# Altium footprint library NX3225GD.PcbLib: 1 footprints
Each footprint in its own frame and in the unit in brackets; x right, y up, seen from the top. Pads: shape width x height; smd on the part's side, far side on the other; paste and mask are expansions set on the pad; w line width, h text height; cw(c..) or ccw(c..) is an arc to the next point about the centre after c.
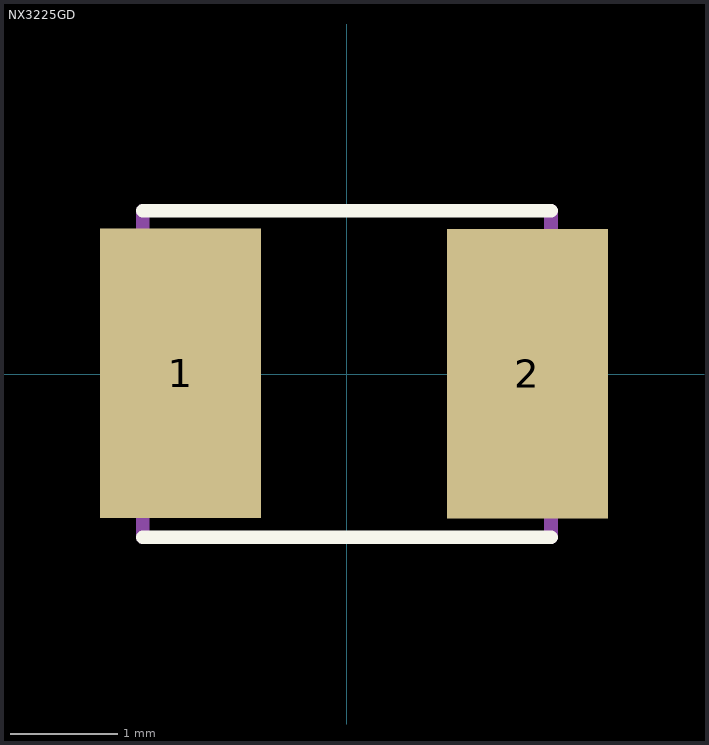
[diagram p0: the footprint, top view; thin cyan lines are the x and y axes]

## NX3225GD [mm]
pads (2):
  rect 1.5x2.7 smd: 1(-1.552,0.007) 2(1.686,0.002)
Top Overlay:
  lines w0.127: -1.905,-1.524 1.905,-1.524 ; -1.905,1.524 1.905,1.524
Mechanical 13:
  lines w0.127: -1.905,-1.524 -1.905,1.524 ; 1.905,-1.524 1.905,1.524
Mechanical 15:
  lines w0.05: -1.905,-1.524 1.905,-1.524 1.905,1.524 -1.905,1.524 -1.905,-1.524
3D body "NX3225GD.STEP": height 1.3, standoff 0, extent -2.433,-1.589 2.567,1.611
